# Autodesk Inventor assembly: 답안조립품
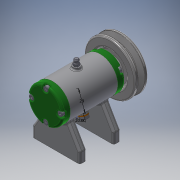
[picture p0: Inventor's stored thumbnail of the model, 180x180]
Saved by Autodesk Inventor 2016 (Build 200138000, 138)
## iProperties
Created: 2018-05
Part Number: 답안조립품
Material: 일반
Document SubType Name: Assembly
Designer: USER
Author: USER
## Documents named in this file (16)
- C:\Users\USER\Desktop\480507V1023\답안조립품.iam
- C:\Users\USER\Desktop\480507V1023\본체.ipt
- C:\Users\USER\Desktop\480507V1023\V벨트풀리.ipt
- C:\Users\USER\Desktop\480507V1023\너트 M8.ipt
- C:\Users\USER\Desktop\480507V1023\니플 M6x0.75.ipt
- C:\Users\USER\Desktop\480507V1023\뒤커버.ipt
- C:\Users\USER\Desktop\480507V1023\베어링 6002.ipt
- C:\Users\USER\Desktop\480507V1023\볼트 M4x12.ipt
- C:\Users\USER\Desktop\480507V1023\볼트 M6x8.ipt
- C:\Users\USER\Desktop\480507V1023\스프링와셔 8.ipt
- C:\Users\USER\Desktop\480507V1023\앞커버.ipt
- C:\Users\USER\Desktop\480507V1023\오일 실 15 25 7.ipt
- C:\Users\USER\Desktop\480507V1023\와셔 6x11.5.ipt
- C:\Users\USER\Desktop\480507V1023\와셔 8x17.ipt
- C:\Users\USER\Desktop\480507V1023\축.ipt
- C:\Users\USER\Desktop\480507V1023\키 3x3x12.ipt
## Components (1 placed, 1 different names)
1. V벨트풀리:1
